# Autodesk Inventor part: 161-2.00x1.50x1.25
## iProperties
Created: 2007-06
Part Number: 161-2.00x1.50x1.25
Document SubType Name: Modeling
Designer: btaylor
Density: 1 g/cm^3
Author: btaylor
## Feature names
1. Revolution1
2. Extrusion1
3. Extrusion2
4. Extrusion3
5. Extrusion4
6. Fillet1
7. Fillet2
8. Fillet3
9. Fillet4
10. Extrusion5
11. Extrusion6
12. Extrusion7
13. Revolution3
14. Extrusion8
15. Fillet5
16. Fillet6
17. Fillet7
18. Fillet8
19. Chamfer1
20. Chamfer2
21. Chamfer3
22. Fillet9
23. Fillet10
24. Fillet11
